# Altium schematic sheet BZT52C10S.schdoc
size 127 x 101 mm
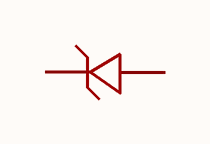
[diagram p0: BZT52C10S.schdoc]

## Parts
ZD?  bzt52c10s_c19334  [SOD-323_L1.8-W1.3-LS2.5-RD]  (value not drawn)

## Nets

Not connected (* = marked no-connect by the designer): ZD? 1(K) 2(A)

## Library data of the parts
ZD? = bzt52c10s_c19334: 二极管配置:1个独立式;稳压值(标称值):10V;稳压值(范围值):9.4V~10.6V;耗散功率(Pd):200mW;; Manufacturer: CJ(江苏长电/长晶); AddInBom: yes; ModelId: db63db13d9e342eb939127d413d6200b; ModelTransform: 104.3305,51.181,0,0,0,0,0,-0.004,0; Diode Configuration: 1个独立式; Zener Voltage(Nom): 10V; Reverse Leakage Current (Ir): 200nA@7V; Pd - Power Dissipation: 200mW; Impedance(Zzt): 20Ω; Impedance(Zzk): 150Ω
